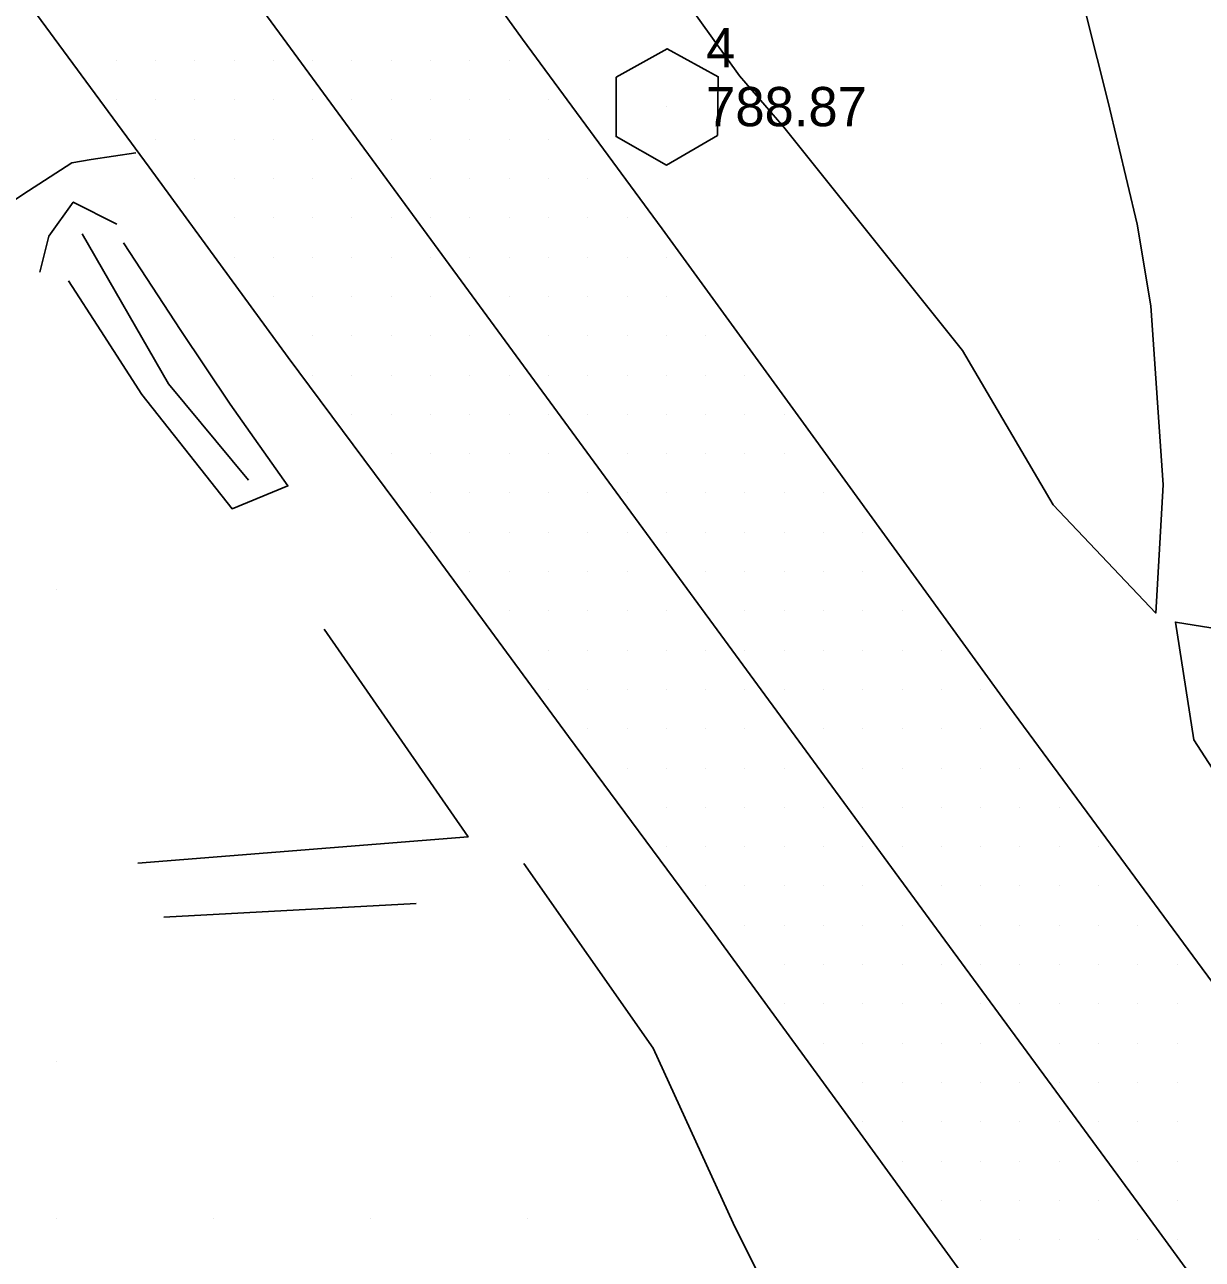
# Model space of a CAD drawing. Extents: x 1762120 to 1766775, y 709485 to 712965.
# Drawn here: x 1763652.9 to 1763727.9, y 711882.5 to 711961 of the extents above; entities that cross this region are included whole.
import ezdxf

# ---------------------------------------------------------------- set-up
doc = ezdxf.new("R2010")
doc.units = 0
for name, color, linetype in [('CTL Primary Horizontal and Vertical CELL', 7, 'Continuous'), ('CTL Primary Horizontal and Vertical Cogo Elevation', 7, 'Continuous'), ('CTL Primary Horizontal and Vertical Cogo Number', 7, 'Continuous'), ('Exist DTM Breakline', 7, 'Continuous'), ('Exist DTM QL2 LIDAR Elevation Point', 7, 'Continuous'), ('Exist DTM Scan Elevation Point', 7, 'Continuous'), ('Exist Roads EOP', 7, 'Continuous'), ('Exist Roads EOT', 7, 'Continuous'), ('PH Exist DTM Breakline', 7, 'Continuous')]:
    doc.layers.add(name, color=color, linetype=linetype)

msp = doc.modelspace()

# ---------------------------------------------------------------- linework, layer by layer
at = {"layer": 'CTL Primary Horizontal and Vertical CELL'}
msp.add_line((1763693.784, 711955.828), (1763693.784, 711955.828), dxfattribs=at)
msp.add_lwpolyline([(1763690.553, 711957.7), (1763693.803, 711959.512), (1763697.053, 711957.725), (1763697.003, 711954), (1763693.753, 711952.112), (1763690.553, 711953.925)], close=True, dxfattribs=at)
at = {"layer": 'Exist DTM Breakline'}
msp.add_lwpolyline([(1763735.985, 711902.144), (1763727.309, 711915.552), (1763726.139, 711923.035), (1763731.574, 711922.167), (1763738.533, 711926.453), (1763742.171, 711928.577), (1763745.869, 711926.616), (1763754.218, 711912.61), (1763750.314, 711906.047), (1763743.531, 711898.065), (1763740.162, 711896.743), (1763735.985, 711902.144)], dxfattribs=at)
at = {"layer": 'Exist DTM QL2 LIDAR Elevation Point'}
for p, q in [((1763654.939, 711925.081), (1763654.939, 711925.081)), ((1763654.939, 711895.078), (1763654.939, 711895.078)), ((1763654.939, 711885.076), (1763654.939, 711885.076)), ((1763664.94, 711885.076), (1763664.94, 711885.076)), ((1763674.941, 711885.076), (1763674.941, 711885.076)), ((1763684.942, 711885.076), (1763684.942, 711885.076))]:
    msp.add_line(p, q, dxfattribs=at)
at = {"layer": 'Exist DTM Scan Elevation Point'}
for p, q in [((1763658.75, 711958.75), (1763658.75, 711958.75)), ((1763661.25, 711958.75), (1763661.25, 711958.75)), ((1763663.75, 711958.75), (1763663.75, 711958.75)), ((1763666.25, 711958.75), (1763666.25, 711958.75)), ((1763668.75, 711958.75), (1763668.75, 711958.75)), ((1763671.25, 711958.75), (1763671.25, 711958.75)), ((1763673.75, 711958.75), (1763673.75, 711958.75)), ((1763676.25, 711958.75), (1763676.25, 711958.75)), ((1763678.75, 711958.75), (1763678.75, 711958.75)), ((1763681.25, 711958.75), (1763681.25, 711958.75)), ((1763683.75, 711958.75), (1763683.75, 711958.75)), ((1763658.75, 711956.25), (1763658.75, 711956.25)), ((1763661.25, 711956.25), (1763661.25, 711956.25)), ((1763663.75, 711956.25), (1763663.75, 711956.25)), ((1763666.25, 711956.25), (1763666.25, 711956.25)), ((1763668.75, 711956.25), (1763668.75, 711956.25)), ((1763671.25, 711956.25), (1763671.25, 711956.25)), ((1763673.75, 711956.25), (1763673.75, 711956.25)), ((1763676.25, 711956.25), (1763676.25, 711956.25)), ((1763678.75, 711956.25), (1763678.75, 711956.25)), ((1763681.25, 711956.25), (1763681.25, 711956.25)), ((1763683.75, 711956.25), (1763683.75, 711956.25)), ((1763686.25, 711956.25), (1763686.25, 711956.25)), ((1763661.25, 711953.75), (1763661.25, 711953.75)), ((1763663.75, 711953.75), (1763663.75, 711953.75)), ((1763666.25, 711953.75), (1763666.25, 711953.75)), ((1763668.75, 711953.75), (1763668.75, 711953.75)), ((1763671.25, 711953.75), (1763671.25, 711953.75)), ((1763676.25, 711953.75), (1763676.25, 711953.75)), ((1763678.75, 711953.75), (1763678.75, 711953.75)), ((1763681.25, 711953.75), (1763681.25, 711953.75)), ((1763683.75, 711953.75), (1763683.75, 711953.75)), ((1763686.25, 711953.75), (1763686.25, 711953.75)), ((1763663.75, 711951.25), (1763663.75, 711951.25)), ((1763666.25, 711951.25), (1763666.25, 711951.25)), ((1763668.75, 711951.25), (1763668.75, 711951.25)), ((1763671.25, 711951.25), (1763671.25, 711951.25)), ((1763673.75, 711951.25), (1763673.75, 711951.25)), ((1763678.75, 711951.25), (1763678.75, 711951.25)), ((1763681.25, 711951.25), (1763681.25, 711951.25)), ((1763683.75, 711951.25), (1763683.75, 711951.25)), ((1763686.25, 711951.25), (1763686.25, 711951.25)), ((1763688.75, 711951.25), (1763688.75, 711951.25)), ((1763666.25, 711948.75), (1763666.25, 711948.75)), ((1763668.75, 711948.75), (1763668.75, 711948.75)), ((1763671.25, 711948.75), (1763671.25, 711948.75)), ((1763673.75, 711948.75), (1763673.75, 711948.75)), ((1763676.25, 711948.75), (1763676.25, 711948.75)), ((1763678.75, 711948.75), (1763678.75, 711948.75)), ((1763681.25, 711948.75), (1763681.25, 711948.75)), ((1763683.75, 711948.75), (1763683.75, 711948.75)), ((1763686.25, 711948.75), (1763686.25, 711948.75)), ((1763688.75, 711948.75), (1763688.75, 711948.75)), ((1763691.25, 711948.75), (1763691.25, 711948.75)), ((1763666.25, 711946.25), (1763666.25, 711946.25)), ((1763668.75, 711946.25), (1763668.75, 711946.25)), ((1763671.25, 711946.25), (1763671.25, 711946.25)), ((1763673.75, 711946.25), (1763673.75, 711946.25)), ((1763676.25, 711946.25), (1763676.25, 711946.25)), ((1763678.75, 711946.25), (1763678.75, 711946.25)), ((1763681.25, 711946.25), (1763681.25, 711946.25)), ((1763683.75, 711946.25), (1763683.75, 711946.25)), ((1763686.25, 711946.25), (1763686.25, 711946.25)), ((1763688.75, 711946.25), (1763688.75, 711946.25)), ((1763691.25, 711946.25), (1763691.25, 711946.25)), ((1763693.75, 711946.25), (1763693.75, 711946.25)), ((1763668.75, 711943.75), (1763668.75, 711943.75)), ((1763671.25, 711943.75), (1763671.25, 711943.75)), ((1763673.75, 711943.75), (1763673.75, 711943.75)), ((1763676.25, 711943.75), (1763676.25, 711943.75)), ((1763678.75, 711943.75), (1763678.75, 711943.75)), ((1763683.75, 711943.75), (1763683.75, 711943.75)), ((1763686.25, 711943.75), (1763686.25, 711943.75)), ((1763688.75, 711943.75), (1763688.75, 711943.75)), ((1763691.25, 711943.75), (1763691.25, 711943.75)), ((1763693.75, 711943.75), (1763693.75, 711943.75)), ((1763671.25, 711941.25), (1763671.25, 711941.25)), ((1763673.75, 711941.25), (1763673.75, 711941.25)), ((1763676.25, 711941.25), (1763676.25, 711941.25)), ((1763678.75, 711941.25), (1763678.75, 711941.25)), ((1763681.25, 711941.25), (1763681.25, 711941.25)), ((1763686.25, 711941.25), (1763686.25, 711941.25)), ((1763688.75, 711941.25), (1763688.75, 711941.25)), ((1763691.25, 711941.25), (1763691.25, 711941.25)), ((1763693.75, 711941.25), (1763693.75, 711941.25)), ((1763696.25, 711941.25), (1763696.25, 711941.25)), ((1763671.25, 711938.75), (1763671.25, 711938.75)), ((1763673.75, 711938.75), (1763673.75, 711938.75)), ((1763676.25, 711938.75), (1763676.25, 711938.75)), ((1763678.75, 711938.75), (1763678.75, 711938.75)), ((1763681.25, 711938.75), (1763681.25, 711938.75)), ((1763683.75, 711938.75), (1763683.75, 711938.75)), ((1763686.25, 711938.75), (1763686.25, 711938.75)), ((1763688.75, 711938.75), (1763688.75, 711938.75)), ((1763691.25, 711938.75), (1763691.25, 711938.75)), ((1763693.75, 711938.75), (1763693.75, 711938.75)), ((1763696.25, 711938.75), (1763696.25, 711938.75)), ((1763698.75, 711938.75), (1763698.75, 711938.75)), ((1763673.75, 711936.25), (1763673.75, 711936.25)), ((1763676.25, 711936.25), (1763676.25, 711936.25)), ((1763678.75, 711936.25), (1763678.75, 711936.25)), ((1763681.25, 711936.25), (1763681.25, 711936.25)), ((1763683.75, 711936.25), (1763683.75, 711936.25)), ((1763686.25, 711936.25), (1763686.25, 711936.25)), ((1763688.75, 711936.25), (1763688.75, 711936.25)), ((1763691.25, 711936.25), (1763691.25, 711936.25)), ((1763693.75, 711936.25), (1763693.75, 711936.25)), ((1763696.25, 711936.25), (1763696.25, 711936.25)), ((1763698.75, 711936.25), (1763698.75, 711936.25)), ((1763701.25, 711936.25), (1763701.25, 711936.25)), ((1763676.25, 711933.75), (1763676.25, 711933.75)), ((1763678.75, 711933.75), (1763678.75, 711933.75)), ((1763681.25, 711933.75), (1763681.25, 711933.75)), ((1763683.75, 711933.75), (1763683.75, 711933.75)), ((1763686.25, 711933.75), (1763686.25, 711933.75)), ((1763691.25, 711933.75), (1763691.25, 711933.75)), ((1763693.75, 711933.75), (1763693.75, 711933.75)), ((1763696.25, 711933.75), (1763696.25, 711933.75)), ((1763698.75, 711933.75), (1763698.75, 711933.75)), ((1763701.25, 711933.75), (1763701.25, 711933.75)), ((1763678.75, 711931.25), (1763678.75, 711931.25)), ((1763681.25, 711931.25), (1763681.25, 711931.25)), ((1763683.75, 711931.25), (1763683.75, 711931.25)), ((1763686.25, 711931.25), (1763686.25, 711931.25)), ((1763688.75, 711931.25), (1763688.75, 711931.25)), ((1763691.25, 711931.25), (1763691.25, 711931.25)), ((1763693.75, 711931.25), (1763693.75, 711931.25)), ((1763696.25, 711931.25), (1763696.25, 711931.25)), ((1763698.75, 711931.25), (1763698.75, 711931.25)), ((1763701.25, 711931.25), (1763701.25, 711931.25)), ((1763703.75, 711931.25), (1763703.75, 711931.25)), ((1763678.75, 711928.75), (1763678.75, 711928.75)), ((1763681.25, 711928.75), (1763681.25, 711928.75)), ((1763683.75, 711928.75), (1763683.75, 711928.75)), ((1763686.25, 711928.75), (1763686.25, 711928.75)), ((1763688.75, 711928.75), (1763688.75, 711928.75)), ((1763691.25, 711928.75), (1763691.25, 711928.75)), ((1763693.75, 711928.75), (1763693.75, 711928.75)), ((1763696.25, 711928.75), (1763696.25, 711928.75)), ((1763698.75, 711928.75), (1763698.75, 711928.75)), ((1763701.25, 711928.75), (1763701.25, 711928.75)), ((1763703.75, 711928.75), (1763703.75, 711928.75)), ((1763706.25, 711928.75), (1763706.25, 711928.75)), ((1763681.25, 711926.25), (1763681.25, 711926.25)), ((1763683.75, 711926.25), (1763683.75, 711926.25)), ((1763686.25, 711926.25), (1763686.25, 711926.25)), ((1763688.75, 711926.25), (1763688.75, 711926.25)), ((1763691.25, 711926.25), (1763691.25, 711926.25)), ((1763696.25, 711926.25), (1763696.25, 711926.25)), ((1763698.75, 711926.25), (1763698.75, 711926.25)), ((1763701.25, 711926.25), (1763701.25, 711926.25)), ((1763703.75, 711926.25), (1763703.75, 711926.25)), ((1763706.25, 711926.25), (1763706.25, 711926.25)), ((1763683.75, 711923.75), (1763683.75, 711923.75)), ((1763686.25, 711923.75), (1763686.25, 711923.75)), ((1763688.75, 711923.75), (1763688.75, 711923.75)), ((1763691.25, 711923.75), (1763691.25, 711923.75)), ((1763693.75, 711923.75), (1763693.75, 711923.75)), ((1763698.75, 711923.75), (1763698.75, 711923.75)), ((1763701.25, 711923.75), (1763701.25, 711923.75)), ((1763703.75, 711923.75), (1763703.75, 711923.75)), ((1763706.25, 711923.75), (1763706.25, 711923.75)), ((1763708.75, 711923.75), (1763708.75, 711923.75)), ((1763686.25, 711921.25), (1763686.25, 711921.25)), ((1763688.75, 711921.25), (1763688.75, 711921.25)), ((1763691.25, 711921.25), (1763691.25, 711921.25)), ((1763693.75, 711921.25), (1763693.75, 711921.25)), ((1763696.25, 711921.25), (1763696.25, 711921.25)), ((1763698.75, 711921.25), (1763698.75, 711921.25)), ((1763701.25, 711921.25), (1763701.25, 711921.25)), ((1763703.75, 711921.25), (1763703.75, 711921.25)), ((1763706.25, 711921.25), (1763706.25, 711921.25)), ((1763708.75, 711921.25), (1763708.75, 711921.25)), ((1763711.25, 711921.25), (1763711.25, 711921.25)), ((1763686.25, 711918.75), (1763686.25, 711918.75)), ((1763688.75, 711918.75), (1763688.75, 711918.75)), ((1763691.25, 711918.75), (1763691.25, 711918.75)), ((1763693.75, 711918.75), (1763693.75, 711918.75)), ((1763696.25, 711918.75), (1763696.25, 711918.75)), ((1763698.75, 711918.75), (1763698.75, 711918.75)), ((1763701.25, 711918.75), (1763701.25, 711918.75)), ((1763703.75, 711918.75), (1763703.75, 711918.75)), ((1763706.25, 711918.75), (1763706.25, 711918.75)), ((1763708.75, 711918.75), (1763708.75, 711918.75)), ((1763711.25, 711918.75), (1763711.25, 711918.75)), ((1763713.75, 711918.75), (1763713.75, 711918.75)), ((1763688.75, 711916.25), (1763688.75, 711916.25)), ((1763691.25, 711916.25), (1763691.25, 711916.25)), ((1763693.75, 711916.25), (1763693.75, 711916.25)), ((1763696.25, 711916.25), (1763696.25, 711916.25)), ((1763698.75, 711916.25), (1763698.75, 711916.25)), ((1763703.75, 711916.25), (1763703.75, 711916.25)), ((1763706.25, 711916.25), (1763706.25, 711916.25)), ((1763708.75, 711916.25), (1763708.75, 711916.25)), ((1763711.25, 711916.25), (1763711.25, 711916.25)), ((1763713.75, 711916.25), (1763713.75, 711916.25)), ((1763691.25, 711913.75), (1763691.25, 711913.75)), ((1763693.75, 711913.75), (1763693.75, 711913.75)), ((1763696.25, 711913.75), (1763696.25, 711913.75)), ((1763698.75, 711913.75), (1763698.75, 711913.75)), ((1763701.25, 711913.75), (1763701.25, 711913.75)), ((1763706.25, 711913.75), (1763706.25, 711913.75)), ((1763708.75, 711913.75), (1763708.75, 711913.75)), ((1763711.25, 711913.75), (1763711.25, 711913.75)), ((1763713.75, 711913.75), (1763713.75, 711913.75)), ((1763716.25, 711913.75), (1763716.25, 711913.75)), ((1763693.75, 711911.25), (1763693.75, 711911.25)), ((1763696.25, 711911.25), (1763696.25, 711911.25)), ((1763698.75, 711911.25), (1763698.75, 711911.25)), ((1763701.25, 711911.25), (1763701.25, 711911.25)), ((1763703.75, 711911.25), (1763703.75, 711911.25)), ((1763706.25, 711911.25), (1763706.25, 711911.25)), ((1763708.75, 711911.25), (1763708.75, 711911.25)), ((1763711.25, 711911.25), (1763711.25, 711911.25)), ((1763713.75, 711911.25), (1763713.75, 711911.25)), ((1763716.25, 711911.25), (1763716.25, 711911.25)), ((1763718.75, 711911.25), (1763718.75, 711911.25)), ((1763693.75, 711908.75), (1763693.75, 711908.75)), ((1763696.25, 711908.75), (1763696.25, 711908.75)), ((1763698.75, 711908.75), (1763698.75, 711908.75)), ((1763701.25, 711908.75), (1763701.25, 711908.75)), ((1763703.75, 711908.75), (1763703.75, 711908.75)), ((1763706.25, 711908.75), (1763706.25, 711908.75)), ((1763708.75, 711908.75), (1763708.75, 711908.75)), ((1763711.25, 711908.75), (1763711.25, 711908.75)), ((1763713.75, 711908.75), (1763713.75, 711908.75)), ((1763716.25, 711908.75), (1763716.25, 711908.75)), ((1763718.75, 711908.75), (1763718.75, 711908.75)), ((1763721.25, 711908.75), (1763721.25, 711908.75)), ((1763696.25, 711906.25), (1763696.25, 711906.25)), ((1763698.75, 711906.25), (1763698.75, 711906.25)), ((1763701.25, 711906.25), (1763701.25, 711906.25)), ((1763703.75, 711906.25), (1763703.75, 711906.25)), ((1763706.25, 711906.25), (1763706.25, 711906.25)), ((1763711.25, 711906.25), (1763711.25, 711906.25)), ((1763713.75, 711906.25), (1763713.75, 711906.25)), ((1763716.25, 711906.25), (1763716.25, 711906.25)), ((1763718.75, 711906.25), (1763718.75, 711906.25)), ((1763721.25, 711906.25), (1763721.25, 711906.25)), ((1763698.75, 711903.75), (1763698.75, 711903.75)), ((1763701.25, 711903.75), (1763701.25, 711903.75)), ((1763703.75, 711903.75), (1763703.75, 711903.75)), ((1763706.25, 711903.75), (1763706.25, 711903.75)), ((1763708.75, 711903.75), (1763708.75, 711903.75)), ((1763713.75, 711903.75), (1763713.75, 711903.75)), ((1763716.25, 711903.75), (1763716.25, 711903.75)), ((1763718.75, 711903.75), (1763718.75, 711903.75)), ((1763721.25, 711903.75), (1763721.25, 711903.75)), ((1763723.75, 711903.75), (1763723.75, 711903.75)), ((1763701.25, 711901.25), (1763701.25, 711901.25)), ((1763703.75, 711901.25), (1763703.75, 711901.25)), ((1763706.25, 711901.25), (1763706.25, 711901.25)), ((1763708.75, 711901.25), (1763708.75, 711901.25)), ((1763711.25, 711901.25), (1763711.25, 711901.25)), ((1763713.75, 711901.25), (1763713.75, 711901.25)), ((1763716.25, 711901.25), (1763716.25, 711901.25)), ((1763718.75, 711901.25), (1763718.75, 711901.25)), ((1763721.25, 711901.25), (1763721.25, 711901.25)), ((1763723.75, 711901.25), (1763723.75, 711901.25)), ((1763726.25, 711901.25), (1763726.25, 711901.25)), ((1763701.25, 711898.75), (1763701.25, 711898.75)), ((1763703.75, 711898.75), (1763703.75, 711898.75)), ((1763706.25, 711898.75), (1763706.25, 711898.75)), ((1763708.75, 711898.75), (1763708.75, 711898.75)), ((1763711.25, 711898.75), (1763711.25, 711898.75)), ((1763713.75, 711898.75), (1763713.75, 711898.75)), ((1763716.25, 711898.75), (1763716.25, 711898.75)), ((1763718.75, 711898.75), (1763718.75, 711898.75)), ((1763721.25, 711898.75), (1763721.25, 711898.75)), ((1763723.75, 711898.75), (1763723.75, 711898.75)), ((1763726.25, 711898.75), (1763726.25, 711898.75)), ((1763703.75, 711896.25), (1763703.75, 711896.25)), ((1763706.25, 711896.25), (1763706.25, 711896.25)), ((1763708.75, 711896.25), (1763708.75, 711896.25)), ((1763711.25, 711896.25), (1763711.25, 711896.25)), ((1763713.75, 711896.25), (1763713.75, 711896.25)), ((1763718.75, 711896.25), (1763718.75, 711896.25)), ((1763721.25, 711896.25), (1763721.25, 711896.25)), ((1763723.75, 711896.25), (1763723.75, 711896.25)), ((1763726.25, 711896.25), (1763726.25, 711896.25)), ((1763706.25, 711893.75), (1763706.25, 711893.75)), ((1763708.75, 711893.75), (1763708.75, 711893.75)), ((1763711.25, 711893.75), (1763711.25, 711893.75)), ((1763713.75, 711893.75), (1763713.75, 711893.75)), ((1763716.25, 711893.75), (1763716.25, 711893.75)), ((1763718.75, 711893.75), (1763718.75, 711893.75)), ((1763721.25, 711893.75), (1763721.25, 711893.75)), ((1763723.75, 711893.75), (1763723.75, 711893.75)), ((1763726.25, 711893.75), (1763726.25, 711893.75)), ((1763706.25, 711891.25), (1763706.25, 711891.25)), ((1763708.75, 711891.25), (1763708.75, 711891.25)), ((1763711.25, 711891.25), (1763711.25, 711891.25)), ((1763713.75, 711891.25), (1763713.75, 711891.25)), ((1763716.25, 711891.25), (1763716.25, 711891.25)), ((1763718.75, 711891.25), (1763718.75, 711891.25)), ((1763721.25, 711891.25), (1763721.25, 711891.25)), ((1763723.75, 711891.25), (1763723.75, 711891.25)), ((1763726.25, 711891.25), (1763726.25, 711891.25)), ((1763708.75, 711888.75), (1763708.75, 711888.75)), ((1763711.25, 711888.75), (1763711.25, 711888.75)), ((1763713.75, 711888.75), (1763713.75, 711888.75)), ((1763716.25, 711888.75), (1763716.25, 711888.75)), ((1763718.75, 711888.75), (1763718.75, 711888.75)), ((1763723.75, 711888.75), (1763723.75, 711888.75)), ((1763726.25, 711888.75), (1763726.25, 711888.75)), ((1763711.25, 711886.25), (1763711.25, 711886.25)), ((1763713.75, 711886.25), (1763713.75, 711886.25)), ((1763716.25, 711886.25), (1763716.25, 711886.25)), ((1763718.75, 711886.25), (1763718.75, 711886.25)), ((1763721.25, 711886.25), (1763721.25, 711886.25)), ((1763726.25, 711886.25), (1763726.25, 711886.25)), ((1763713.75, 711883.75), (1763713.75, 711883.75)), ((1763716.25, 711883.75), (1763716.25, 711883.75)), ((1763718.75, 711883.75), (1763718.75, 711883.75)), ((1763721.25, 711883.75), (1763721.25, 711883.75)), ((1763723.75, 711883.75), (1763723.75, 711883.75)), ((1763726.25, 711883.75), (1763726.25, 711883.75))]:
    msp.add_line(p, q, dxfattribs=at)
at = {"layer": 'Exist Roads EOP'}
for points in [[(1763747.792, 711873.595), (1763737.702, 711887.008), (1763729.105, 711899.303), (1763715.58, 711917.631), (1763702.317, 711935.933), (1763693.483, 711948.048), (1763684.591, 711960.119), (1763669.292, 711981.364), (1763660.187, 711993.271), (1763651.225, 712005.282), (1763642.443, 712017.422), (1763633.554, 712029.485), (1763624.616, 712041.511), (1763615.857, 712053.664), (1763612.498, 712058.49)], [(1763595.29, 712041.368), (1763607.489, 712024.346), (1763616.553, 712012.418), (1763625.455, 712000.365), (1763634.299, 711988.267), (1763643.197, 711976.207), (1763651.971, 711964.052), (1763660.841, 711951.968), (1763669.699, 711939.873), (1763678.637, 711927.836), (1763687.522, 711915.759), (1763696.461, 711903.716), (1763705.306, 711891.607), (1763717.65, 711874.591), (1763723.492, 711866.658), (1763726.497, 711862.285), (1763727.492, 711860.223), (1763727.651, 711858.847), (1763727.52, 711858.179), (1763728.735, 711856.956)]]:
    msp.add_lwpolyline(points, dxfattribs=at)
at = {"layer": 'Exist Roads EOT'}
msp.add_lwpolyline([(1763567.774, 712098.528), (1763588.559, 712070.294), (1763609.163, 712042.272), (1763632.355, 712010.627), (1763643.855, 711994.92), (1763653.597, 711981.678), (1763666.282, 711964.42), (1763694.364, 711926.12), (1763710.715, 711903.835), (1763724.536, 711885.027), (1763739.133, 711865.028)], dxfattribs=at)
at = {"layer": 'PH Exist DTM Breakline'}
msp.add_line((1763661.783, 711904.26), (1763677.841, 711905.139), dxfattribs=at)
for points in [[(1763708.731, 711981.391), (1763714.626, 711976.063), (1763717.46, 711970.371), (1763719.786, 711964.381), (1763721.869, 711956.111), (1763723.706, 711948.343), (1763724.578, 711943.164), (1763725.353, 711931.775), (1763724.892, 711923.608), (1763718.363, 711930.489), (1763712.59, 711940.317), (1763701.223, 711954.51), (1763698.406, 711957.792), (1763695.083, 711962.429), (1763692.893, 711965.673), (1763690.412, 711968.299)], [(1763595.498, 711904.499), (1763599.444, 711906.307), (1763606.026, 711910.403), (1763611.634, 711913.779), (1763618.754, 711919.187), (1763624.535, 711924.36), (1763631.255, 711930.551), (1763636.28, 711937.591), (1763645.396, 711945.245), (1763652.805, 711950.228), (1763655.92, 711952.242), (1763657.15, 711952.455), (1763660.002, 711952.885)], [(1763658.798, 711948.345), (1763656.019, 711949.75), (1763654.469, 711947.579), (1763653.885, 711945.286)], [(1763656.591, 711947.74), (1763662.07, 711938.198), (1763667.176, 711932.06)], [(1763659.207, 711947.152), (1763662.862, 711941.579), (1763666.004, 711936.908), (1763669.675, 711931.701), (1763666.125, 711930.245), (1763660.381, 711937.504), (1763657.771, 711941.57), (1763655.724, 711944.742)], [(1763671.976, 711922.579), (1763681.135, 711909.365), (1763660.125, 711907.703)], [(1763684.68, 711907.684), (1763692.908, 711895.927), (1763697.998, 711884.799), (1763701.685, 711877.384), (1763703.82, 711871.003), (1763705.897, 711865.361)]]:
    msp.add_lwpolyline(points, dxfattribs=at)

# ---------------------------------------------------------------- texts
at = {"layer": 'CTL Primary Horizontal and Vertical Cogo Elevation'}
msp.add_text('788.87', height=2.5, dxfattribs=at).set_placement((1763696.284, 711954.578))
at = {"layer": 'CTL Primary Horizontal and Vertical Cogo Number'}
msp.add_text('4', height=2.5, dxfattribs=at).set_placement((1763696.284, 711958.328))

doc.saveas('drawing.dxf')
